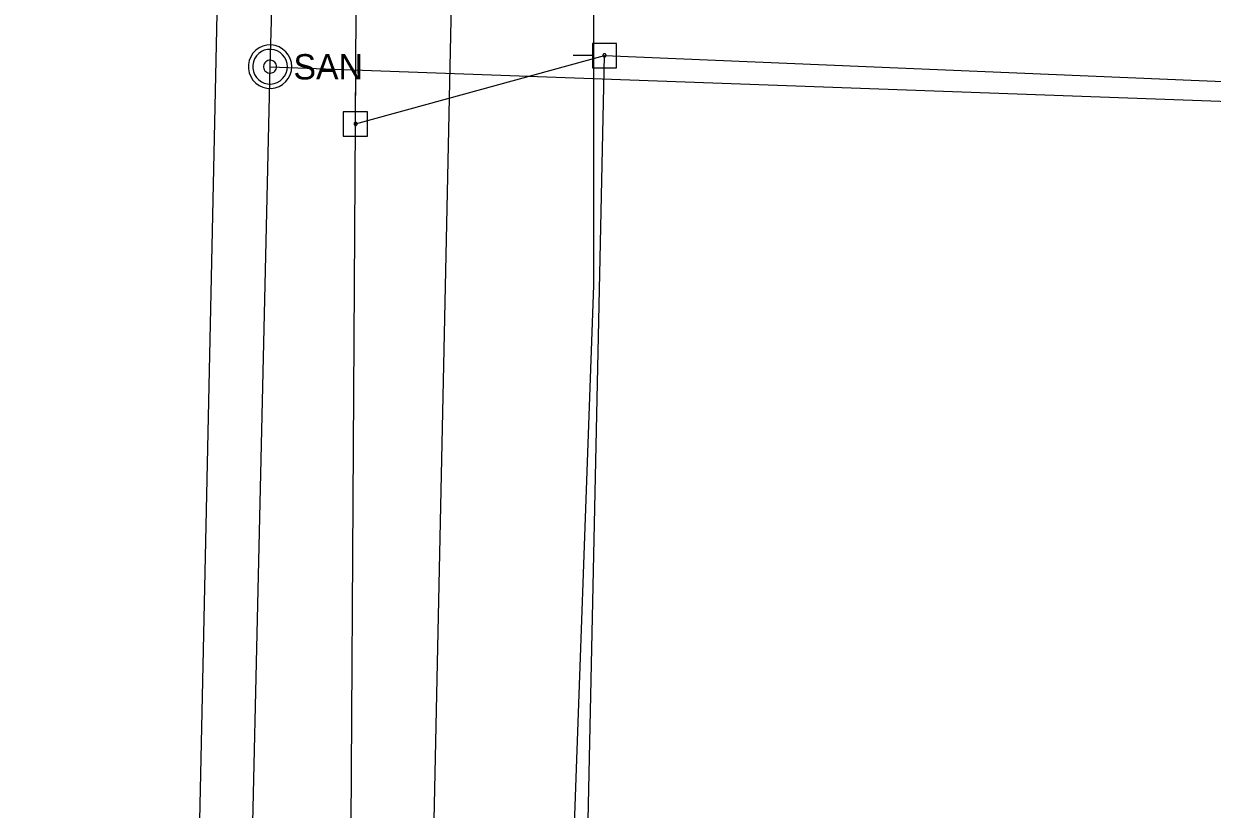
# Model space of a CAD drawing. Extents: x 596028 to 606371, y 330010 to 403088.
# Drawn here: x 596450.8 to 596631.6, y 343458 to 343577.5 of the extents above; entities that cross this region are included whole.
import ezdxf

# ---------------------------------------------------------------- set-up
doc = ezdxf.new("R2010")
doc.units = 0
for name, color, linetype in [('E_UTL_EPowerPole', 7, 'Continuous'), ('E_UTL_FO_UG', 7, 'Continuous'), ('E_UTL_G_UG', 7, 'Continuous'), ('E_UTL_Overhead', 7, 'Continuous'), ('E_UTL_SAN_MH', 7, 'Continuous'), ('E_UTL_SAN_UG', 7, 'Continuous'), ('E_UTL_W_UG', 7, 'Continuous')]:
    doc.layers.add(name, color=color, linetype=linetype)

msp = doc.modelspace()

# ---------------------------------------------------------------- linework, layer by layer
at = {"layer": 'E_UTL_EPowerPole'}
for points in [[(596541, 343574.53), (596537.31, 343574.53)], [(596537.31, 343574.53), (596537.31, 343570.84)], [(596541, 343570.84), (596541, 343574.53)], [(596537.31, 343572.68), (596534.4, 343572.68)], [(596539.15, 343572.95), (596539.1, 343572.95), (596539.06, 343572.94), (596539.02, 343572.92), (596538.98, 343572.89), (596538.96, 343572.85), (596538.93, 343572.81), (596538.92, 343572.77), (596538.91, 343572.73), (596538.91, 343572.68), (596538.92, 343572.64), (596538.94, 343572.6), (596538.97, 343572.56), (596539, 343572.53), (596539.04, 343572.5), (596539.08, 343572.49), (596539.13, 343572.48), (596539.17, 343572.48), (596539.22, 343572.49), (596539.26, 343572.5), (596539.3, 343572.53), (596539.33, 343572.56), (596539.36, 343572.6), (596539.37, 343572.64), (596539.39, 343572.68), (596539.39, 343572.73), (596539.38, 343572.77), (596539.37, 343572.81), (596539.34, 343572.85), (596539.31, 343572.89), (596539.28, 343572.92), (596539.24, 343572.94), (596539.19, 343572.95), (596539.15, 343572.95)], [(596537.31, 343570.84), (596541, 343570.84)], [(596501.26, 343564.13), (596501.26, 343567.04)], [(596503.1, 343564.13), (596499.41, 343564.13)], [(596499.41, 343564.13), (596499.41, 343560.44)], [(596503.1, 343560.44), (596503.1, 343564.13)], [(596501.53, 343562.28), (596501.52, 343562.33), (596501.51, 343562.37), (596501.49, 343562.41), (596501.46, 343562.45), (596501.43, 343562.48), (596501.39, 343562.5), (596501.35, 343562.52), (596501.3, 343562.52), (596501.26, 343562.52), (596501.21, 343562.51), (596501.17, 343562.49), (596501.13, 343562.46), (596501.1, 343562.43), (596501.08, 343562.39), (596501.06, 343562.35), (596501.05, 343562.31), (596501.05, 343562.26), (596501.06, 343562.22), (596501.08, 343562.17), (596501.1, 343562.14), (596501.13, 343562.1), (596501.17, 343562.08), (596501.21, 343562.06), (596501.26, 343562.05), (596501.3, 343562.05), (596501.35, 343562.05), (596501.39, 343562.07), (596501.43, 343562.09), (596501.46, 343562.12), (596501.49, 343562.16), (596501.51, 343562.2), (596501.52, 343562.24), (596501.53, 343562.28)], [(596499.41, 343560.44), (596503.1, 343560.44)]]:
    msp.add_lwpolyline(points, dxfattribs=at)
at = {"layer": 'E_UTL_FO_UG'}
msp.add_lwpolyline([(596623.2, 343221.5), (596591.63, 343263.11), (596564.61, 343305.57), (596536.54, 343354.45), (596533.7, 343373.6), (596535.42, 343430.17), (596534.15, 343442.91), (596537.51, 343537.7), (596537.51, 343588.84), (596540.54, 343656.31), (596541, 343722.96), (596544.11, 343796.55), (596541.22, 343839.02), (596528.82, 343853.36)], dxfattribs=at)
at = {"layer": 'E_UTL_G_UG'}
msp.add_line((596512.85, 343437.73), (596515.88, 343580.52), dxfattribs=at)
at = {"layer": 'E_UTL_Overhead'}
for p, q in [((596501.29, 343562.28), (596539.15, 343572.71)), ((596534.56, 343356.08), (596539.15, 343572.71)), ((596539.15, 343572.71), (596688.01, 343566.43))]:
    msp.add_line(p, q, dxfattribs=at)
msp.add_lwpolyline([(596433.09, 343338.93), (596500.33, 343406.37), (596501.29, 343562.28), (596502.11, 343708.76), (596502.83, 343809.08), (596507.18, 343924.33)], dxfattribs=at)
at = {"layer": 'E_UTL_SAN_MH'}
for points in [[(596491.57, 343570.99), (596491.51, 343571.62), (596491.33, 343572.22), (596491.04, 343572.78), (596490.65, 343573.27), (596490.18, 343573.68), (596489.64, 343573.99), (596489.04, 343574.2), (596488.42, 343574.29), (596487.8, 343574.26), (596487.19, 343574.11), (596486.62, 343573.85), (596486.1, 343573.48), (596485.67, 343573.03), (596485.33, 343572.5), (596485.1, 343571.92), (596484.98, 343571.3), (596484.98, 343570.68), (596485.1, 343570.06), (596485.33, 343569.48), (596485.67, 343568.95), (596486.1, 343568.5), (596486.62, 343568.13), (596487.19, 343567.87), (596487.8, 343567.72), (596488.42, 343567.69), (596489.04, 343567.78), (596489.64, 343567.99), (596490.18, 343568.3), (596490.65, 343568.71), (596491.04, 343569.21), (596491.33, 343569.76), (596491.51, 343570.37), (596491.57, 343570.99)], [(596490.91, 343570.99), (596490.86, 343571.49), (596490.72, 343571.97), (596490.49, 343572.42), (596490.18, 343572.81), (596489.8, 343573.14), (596489.36, 343573.39), (596488.89, 343573.56), (596488.39, 343573.63), (596487.89, 343573.6), (596487.4, 343573.49), (596486.95, 343573.28), (596486.54, 343572.99), (596486.19, 343572.62), (596485.92, 343572.2), (596485.73, 343571.73), (596485.64, 343571.24), (596485.64, 343570.74), (596485.73, 343570.25), (596485.92, 343569.78), (596486.19, 343569.36), (596486.54, 343569), (596486.95, 343568.7), (596487.4, 343568.5), (596487.89, 343568.38), (596488.39, 343568.35), (596488.89, 343568.43), (596489.36, 343568.59), (596489.8, 343568.84), (596490.18, 343569.17), (596490.49, 343569.56), (596490.72, 343570.01), (596490.86, 343570.49), (596490.91, 343570.99)], [(596489.26, 343570.99), (596489.24, 343571.18), (596489.18, 343571.36), (596489.1, 343571.53), (596488.98, 343571.67), (596488.84, 343571.8), (596488.68, 343571.89), (596488.5, 343571.95), (596488.31, 343571.98), (596488.12, 343571.97), (596487.94, 343571.93), (596487.77, 343571.85), (596487.62, 343571.74), (596487.49, 343571.6), (596487.39, 343571.44), (596487.32, 343571.27), (596487.28, 343571.09), (596487.28, 343570.9), (596487.32, 343570.71), (596487.39, 343570.54), (596487.49, 343570.38), (596487.62, 343570.24), (596487.77, 343570.13), (596487.94, 343570.06), (596488.12, 343570.01), (596488.31, 343570), (596488.5, 343570.03), (596488.68, 343570.09), (596488.84, 343570.18), (596488.98, 343570.31), (596489.1, 343570.46), (596489.18, 343570.62), (596489.24, 343570.8), (596489.26, 343570.99)]]:
    msp.add_lwpolyline(points, dxfattribs=at)
at = {"layer": 'E_UTL_SAN_UG'}
msp.add_line((596488.27, 343570.99), (596723.86, 343562.43), dxfattribs=at)
msp.add_lwpolyline([(596474.29, 343299.7), (596483.68, 343369.67), (596488.27, 343570.99), (596492.83, 343728.76), (596493.38, 343805.11), (596496.8, 343910.62), (596505.55, 344309.74)], dxfattribs=at)
at = {"layer": 'E_UTL_W_UG'}
msp.add_lwpolyline([(596502.84, 343266.57), (596534.18, 343288.36), (596475.61, 343364.22), (596483.72, 343742), (596509.64, 343741.09)], dxfattribs=at)

# ---------------------------------------------------------------- texts
at = {"layer": 'E_UTL_SAN_MH'}
msp.add_text('SAN', height=3.849, dxfattribs=at).set_placement((596491.83, 343569.05))

doc.saveas('drawing.dxf')
